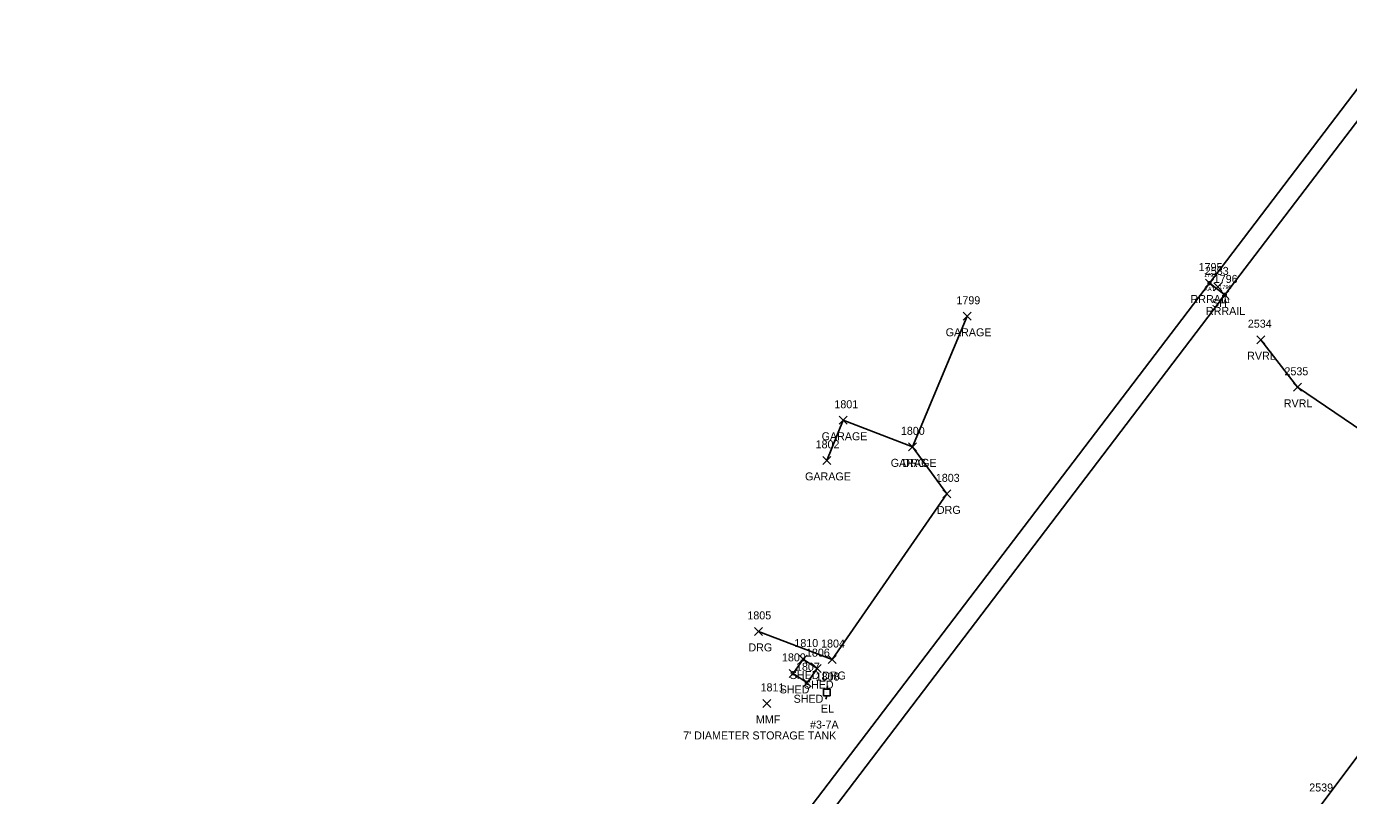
# Model space of a CAD drawing. Extents: x 1767353 to 1772625, y 740790 to 747702.
# Drawn here: x 1772120.9 to 1772451.2, y 747504.6 to 747696.7 of the extents above; entities that cross this region are included whole.
import ezdxf

# ---------------------------------------------------------------- set-up
doc = ezdxf.new("R2010")
doc.units = 0
for name, color, linetype in [('B_A', 7, 'Continuous'), ('B_I', 7, 'Continuous'), ('B_TIC', 7, 'Continuous'), ('BSUBM', 7, 'Continuous'), ('L_A', 7, 'Continuous'), ('L_C', 7, 'Continuous'), ('L_I', 7, 'Continuous'), ('L_TIC', 7, 'Continuous'), ('LAWE', 7, 'Continuous'), ('LBC', 7, 'Continuous'), ('LFNC', 7, 'Continuous'), ('R_A', 7, 'Continuous'), ('R_I', 7, 'Continuous'), ('R_TIC', 7, 'Continuous'), ('RDG', 7, 'Continuous'), ('RR', 7, 'Continuous'), ('U_A', 7, 'Continuous'), ('U_C', 7, 'Continuous'), ('U_I', 7, 'Continuous'), ('UEPT', 7, 'Continuous')]:
    doc.layers.add(name, color=color, linetype=linetype)

msp = doc.modelspace()

# ---------------------------------------------------------------- linework, layer by layer
at = {"layer": 'B_TIC'}
for p, q in [((1772416.45, 747632.57), (1772416.52, 747632.57)), ((1772420.29, 747629.6), (1772420.36, 747629.6))]:
    msp.add_line(p, q, dxfattribs=at)
for points in [[(1772415.94, 747632.57), (1772416.94, 747632.57)], [(1772416.44, 747632.07), (1772416.44, 747633.07)], [(1772420.28, 747629.1), (1772420.28, 747630.1)], [(1772419.78, 747629.6), (1772420.78, 747629.6)]]:
    msp.add_lwpolyline(points, dxfattribs=at)
at = {"layer": 'BSUBM'}
msp.add_lwpolyline([(1772416.44, 747632.57), (1772420.28, 747629.6)], dxfattribs=at)
at = {"layer": 'L_TIC'}
for points in [[(1772417.57, 747630.6), (1772419.57, 747632.6)], [(1772419.57, 747630.6), (1772417.57, 747632.6)], [(1772354.94, 747623.27), (1772356.94, 747625.27)], [(1772356.94, 747623.27), (1772354.94, 747625.27)], [(1772428.31, 747617.42), (1772430.31, 747619.42)], [(1772430.31, 747617.42), (1772428.31, 747619.42)], [(1772437.46, 747605.53), (1772439.46, 747607.53)], [(1772439.46, 747605.53), (1772437.46, 747607.53)], [(1772323.95, 747597.3), (1772325.95, 747599.3)], [(1772325.95, 747597.3), (1772323.95, 747599.3)], [(1772341.22, 747590.66), (1772343.22, 747592.66)], [(1772343.22, 747590.66), (1772341.22, 747592.66)], [(1772319.82, 747587.28), (1772321.82, 747589.28)], [(1772321.82, 747587.28), (1772319.82, 747589.28)], [(1772313.96, 747537.66), (1772315.96, 747539.66)], [(1772315.96, 747537.66), (1772313.96, 747539.66)], [(1772313.96, 747537.66), (1772315.96, 747539.66)], [(1772315.96, 747537.66), (1772313.96, 747539.66)], [(1772311.43, 747534.08), (1772313.43, 747536.08)], [(1772313.43, 747534.08), (1772311.43, 747536.08)], [(1772317.47, 747535.26), (1772319.47, 747537.26)], [(1772319.47, 747535.26), (1772317.47, 747537.26)], [(1772317.47, 747535.26), (1772319.47, 747537.26)], [(1772319.47, 747535.26), (1772317.47, 747537.26)], [(1772314.92, 747531.74), (1772316.92, 747533.74)], [(1772316.92, 747531.74), (1772314.92, 747533.74)], [(1772304.85, 747526.58), (1772306.85, 747528.58)], [(1772306.85, 747526.58), (1772304.85, 747528.58)]]:
    msp.add_lwpolyline(points, dxfattribs=at)
at = {"layer": 'LAWE'}
msp.add_lwpolyline([(1772429.31, 747618.42), (1772438.46, 747606.53), (1772454.79, 747595.51), (1772480.99, 747587.69), (1772505.54, 747577.42)], dxfattribs=at)
at = {"layer": 'LBC'}
for points in [[(1772355.94, 747624.27), (1772342.22, 747591.66), (1772324.95, 747598.3), (1772320.82, 747588.28)], [(1772318.47, 747536.26), (1772315.92, 747532.74), (1772312.43, 747535.08), (1772314.96, 747538.66)], [(1772318.47, 747536.26), (1772314.96, 747538.66)]]:
    msp.add_lwpolyline(points, dxfattribs=at)
at = {"layer": 'LFNC'}
msp.add_lwpolyline([(1772375.15, 747411.53), (1772444.65, 747502.58), (1772497.04, 747572.52)], dxfattribs=at)
at = {"layer": 'R_TIC'}
for points in [[(1772415.44, 747631.57), (1772417.44, 747633.57)], [(1772417.44, 747631.57), (1772415.44, 747633.57)], [(1772419.28, 747628.6), (1772421.28, 747630.6)], [(1772421.28, 747628.6), (1772419.28, 747630.6)], [(1772341.22, 747590.66), (1772343.22, 747592.66)], [(1772343.22, 747590.66), (1772341.22, 747592.66)], [(1772349.87, 747578.92), (1772351.87, 747580.92)], [(1772351.87, 747578.92), (1772349.87, 747580.92)], [(1772302.77, 747544.57), (1772304.77, 747546.57)], [(1772304.77, 747544.57), (1772302.77, 747546.57)], [(1772321.2, 747537.54), (1772323.2, 747539.54)], [(1772323.2, 747537.54), (1772321.2, 747539.54)]]:
    msp.add_lwpolyline(points, dxfattribs=at)
at = {"layer": 'RDG'}
msp.add_lwpolyline([(1772342.22, 747591.66), (1772350.87, 747579.92), (1772322.2, 747538.54), (1772303.77, 747545.57)], dxfattribs=at)
at = {"layer": 'RR'}
for points in [[(1771960.76, 746895.46), (1771976.57, 746936.04), (1771991.76, 746972.7), (1772003.71, 747000.43), (1772025.97, 747048.7), (1772044.45, 747086.9), (1772066.42, 747128.97), (1772087.05, 747166.47), (1772110.84, 747207.58), (1772133.43, 747244.66), (1772156.72, 747281.04), (1772175.9, 747310.14), (1772194.46, 747336.8), (1772219.05, 747370.3), (1772232.59, 747389.89), (1772256.2, 747421.67), (1772277.77, 747450.57), (1772416.44, 747632.57), (1772465.26, 747696.66)], [(1771963.49, 746888.34), (1771980.41, 746932.18), (1771994.59, 746967.04), (1772007.72, 746997.13), (1772029.49, 747045.02), (1772048.72, 747084.09), (1772070.77, 747126.16), (1772091.38, 747163.68), (1772115.23, 747205.31), (1772138.09, 747242.79), (1772160.69, 747278.1), (1772180.23, 747307.44), (1772199.65, 747335.62), (1772224.35, 747370.12), (1772238.38, 747389.48), (1772261.28, 747420.38), (1772281.38, 747447.15), (1772420.28, 747629.6), (1772469.26, 747693.79)]]:
    msp.add_lwpolyline(points, dxfattribs=at)
at = {"layer": 'UEPT'}
for p, q in [((1772320, 747529.46), (1772320, 747531.13)), ((1772320, 747531.13), (1772321.66, 747531.13)), ((1772321, 747531.96), (1772320.83, 747531.13)), ((1772321.66, 747531.13), (1772321.66, 747529.46)), ((1772321.66, 747529.46), (1772320, 747529.46)), ((1772320.58, 747528.63), (1772320.83, 747529.46)), ((1772320.83, 747530.29), (1772320.83, 747530.29))]:
    msp.add_line(p, q, dxfattribs=at)

# ---------------------------------------------------------------- texts
at = {"layer": 'B_A'}
for p in [(1772415.15, 747630.57), (1772418.99, 747627.6)]:
    msp.add_text('XAT', height=1, dxfattribs=at).set_placement(p)
at = {"layer": 'B_I'}
for s, p in [('1795', (1772415.1, 747634.07)), ('1796', (1772418.91, 747631.1))]:
    msp.add_text(s, height=1, dxfattribs=at).set_placement(p)
at = {"layer": 'L_A'}
for s, p in [('SH', (1772417.06, 747626.6)), ('GARAGE', (1772350.54, 747619.27)), ('RVRL', (1772425.88, 747613.42)), ('RVRL', (1772435.03, 747601.53)), ('GARAGE', (1772319.55, 747593.3)), ('GARAGE', (1772336.82, 747586.66)), ('GARAGE', (1772315.42, 747583.28)), ('SHED', (1772311.6, 747533.66)), ('SHED', (1772311.6, 747533.66)), ('SHED', (1772309.07, 747530.08)), ('SHED', (1772315.11, 747531.26)), ('SHED', (1772315.11, 747531.26)), ('SHED', (1772312.55, 747527.74)), ('MMF', (1772303.14, 747522.58))]:
    msp.add_text(s, height=2, dxfattribs=at).set_placement(p)
at = {"layer": 'L_C'}
msp.add_text("7' DIAMETER STORAGE TANK", height=2, dxfattribs=at).set_placement((1772284.97, 747518.58))
at = {"layer": 'L_I'}
for s, p in [('2533', (1772415.31, 747634.6)), ('1799', (1772353.24, 747627.27)), ('2534', (1772426.05, 747621.42)), ('2535', (1772435.2, 747609.53)), ('1801', (1772322.74, 747601.3)), ('1800', (1772339.36, 747594.66)), ('1802', (1772318.05, 747591.28)), ('1810', (1772312.75, 747541.66)), ('1810', (1772312.75, 747541.66)), ('1806', (1772315.64, 747539.26)), ('1806', (1772315.64, 747539.26)), ('1809', (1772309.65, 747538.08)), ('1807', (1772313.15, 747535.74)), ('1811', (1772304.3, 747530.58)), ('2539', (1772441.39, 747505.58))]:
    msp.add_text(s, height=2, dxfattribs=at).set_placement(p)
at = {"layer": 'R_A'}
for s, p in [('RRRAIL', (1772411.73, 747627.57)), ('RRRAIL', (1772415.58, 747624.6)), ('DRG', (1772339.71, 747586.66)), ('DRG', (1772348.35, 747574.92)), ('DRG', (1772301.26, 747540.57)), ('DRG', (1772319.68, 747533.54))]:
    msp.add_text(s, height=2, dxfattribs=at).set_placement(p)
at = {"layer": 'R_I'}
for s, p in [('1795', (1772413.75, 747635.57)), ('1796', (1772417.54, 747632.6)), ('1800', (1772339.36, 747594.66)), ('1803', (1772348.09, 747582.92)), ('1805', (1772301, 747548.57)), ('1804', (1772319.42, 747541.54))]:
    msp.add_text(s, height=2, dxfattribs=at).set_placement(p)
at = {"layer": 'U_A'}
msp.add_text('EL', height=2, dxfattribs=at).set_placement((1772319.36, 747525.29))
at = {"layer": 'U_C'}
msp.add_text('#3-7A', height=2, dxfattribs=at).set_placement((1772316.66, 747521.29))
at = {"layer": 'U_I'}
msp.add_text('1808', height=2, dxfattribs=at).set_placement((1772318.06, 747533.29))

doc.saveas('drawing.dxf')
